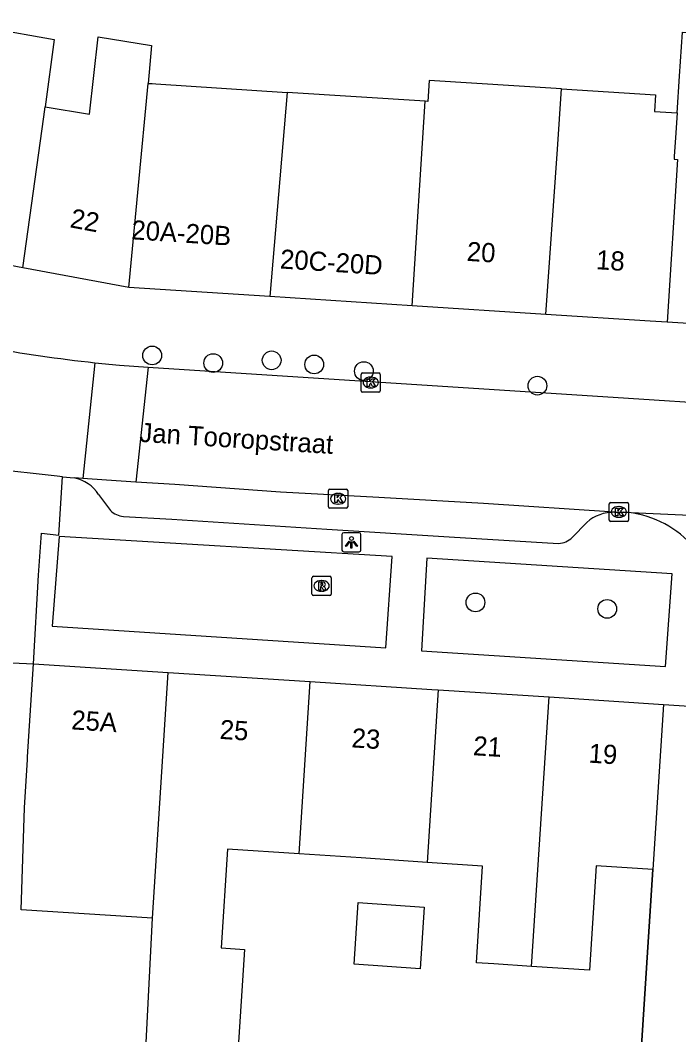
# Model space of a CAD drawing. Extents: x 163010 to 163853, y 382793 to 383982.
# Drawn here: x 163273.4 to 163307.7, y 383427.7 to 383480.6 of the extents above; entities that cross this region are included whole.
import ezdxf

# ---------------------------------------------------------------- set-up
doc = ezdxf.new("R2010")
doc.units = 0
for name, color, linetype in [('IMGEO_Boom', 7, 'Continuous'), ('IMGEO_Kolk', 7, 'Continuous'), ('IMGEO_Lichtpunt', 7, 'Continuous'), ('IMGEO_Muur', 7, 'Continuous'), ('IMGEO_Openbare_ruimte_label', 7, 'Continuous'), ('IMGEO_Pand', 7, 'Continuous'), ('IMGEO_Pand_nummerreeks', 7, 'Continuous'), ('IMGEO_Rijbaan_lokaal_open', 7, 'Continuous'), ('IMGEO_Rioolput', 7, 'Continuous'), ('IMGEO_Voetpad_open', 7, 'Continuous')]:
    doc.layers.add(name, color=color, linetype=linetype)

msp = doc.modelspace()

# ---------------------------------------------------------------- linework, layer by layer
at = {"layer": 'IMGEO_Boom'}
for centre in [(163280.281, 383463.141), (163283.462, 383462.743), (163286.509, 383462.887), (163288.727, 383462.671), (163291.316, 383462.325), (163300.361, 383461.565), (163297.132, 383450.267), (163303.999, 383449.932)]:
    msp.add_circle(centre, 0.489, dxfattribs=at)
at = {"layer": 'IMGEO_Kolk'}
for p, q in [((163291.172, 383461.304), (163291.172, 383462.156)), ((163291.247, 383462.23), (163292.099, 383462.23)), ((163291.66, 383462.01), (163291.685, 383462.01)), ((163292.173, 383462.156), (163292.173, 383461.304)), ((163291.683, 383461.45), (163291.658, 383461.45)), ((163292.099, 383461.23), (163291.247, 383461.23)), ((163289.474, 383455.247), (163289.474, 383456.099)), ((163289.549, 383456.173), (163290.401, 383456.173)), ((163290.475, 383456.099), (163290.475, 383455.247)), ((163289.962, 383455.953), (163289.987, 383455.953)), ((163290.401, 383455.173), (163289.549, 383455.173)), ((163289.985, 383455.393), (163289.96, 383455.393)), ((163304.107, 383454.557), (163304.107, 383455.409)), ((163304.182, 383455.483), (163305.034, 383455.483)), ((163304.595, 383455.263), (163304.62, 383455.263)), ((163305.108, 383455.409), (163305.108, 383454.557)), ((163305.034, 383454.483), (163304.182, 383454.483)), ((163304.618, 383454.703), (163304.593, 383454.703))]:
    msp.add_line(p, q, dxfattribs=at)
for points in [[(163291.172, 383461.304), (163291.172, 383462.156)], [(163291.247, 383462.23), (163292.099, 383462.23)], [(163291.493, 383461.93), (163291.616, 383461.93), (163291.616, 383461.779), (163291.746, 383461.93), (163291.91, 383461.93), (163291.764, 383461.779), (163291.917, 383461.53), (163291.765, 383461.53), (163291.68, 383461.694), (163291.616, 383461.627), (163291.616, 383461.53), (163291.493, 383461.53), (163291.493, 383461.93)], [(163292.173, 383462.156), (163292.173, 383461.304)], [(163292.099, 383461.23), (163291.247, 383461.23)], [(163289.474, 383455.247), (163289.474, 383456.099)], [(163289.549, 383456.173), (163290.401, 383456.173)], [(163290.475, 383456.099), (163290.475, 383455.247)], [(163289.795, 383455.873), (163289.918, 383455.873), (163289.918, 383455.722), (163290.048, 383455.873), (163290.212, 383455.873), (163290.066, 383455.722), (163290.219, 383455.473), (163290.067, 383455.473), (163289.982, 383455.637), (163289.918, 383455.57), (163289.918, 383455.473), (163289.795, 383455.473), (163289.795, 383455.873)], [(163290.401, 383455.173), (163289.549, 383455.173)], [(163304.107, 383454.557), (163304.107, 383455.409)], [(163304.182, 383455.483), (163305.034, 383455.483)], [(163304.428, 383455.183), (163304.551, 383455.183), (163304.551, 383455.032), (163304.681, 383455.183), (163304.845, 383455.183), (163304.699, 383455.032), (163304.852, 383454.783), (163304.7, 383454.783), (163304.615, 383454.947), (163304.551, 383454.88), (163304.551, 383454.783), (163304.428, 383454.783), (163304.428, 383455.183)], [(163305.108, 383455.409), (163305.108, 383454.557)], [(163305.034, 383454.483), (163304.182, 383454.483)]]:
    msp.add_lwpolyline(points, dxfattribs=at)
for centre, start, end in [((163291.249, 383462.154), 91.552, 178.448), ((163291.249, 383462.154), 91.552, 178.448), ((163292.097, 383462.154), 1.552, 88.448), ((163292.097, 383462.154), 1.552, 88.448), ((163291.249, 383461.306), 181.552, 268.448), ((163291.249, 383461.306), 181.552, 268.448), ((163292.097, 383461.306), 271.552, 358.448), ((163292.097, 383461.306), 271.552, 358.448), ((163289.551, 383456.097), 91.552, 178.448), ((163289.551, 383456.097), 91.552, 178.448), ((163290.399, 383456.097), 1.552, 88.448), ((163290.399, 383456.097), 1.552, 88.448), ((163289.551, 383455.249), 181.552, 268.448), ((163289.551, 383455.249), 181.552, 268.448), ((163290.399, 383455.249), 271.552, 358.448), ((163290.399, 383455.249), 271.552, 358.448), ((163304.184, 383455.407), 91.552, 178.448), ((163304.184, 383455.407), 91.552, 178.448), ((163305.032, 383455.407), 1.552, 88.448), ((163305.032, 383455.407), 1.552, 88.448), ((163304.184, 383454.559), 181.552, 268.448), ((163304.184, 383454.559), 181.552, 268.448), ((163305.032, 383454.559), 271.552, 358.448), ((163305.032, 383454.559), 271.552, 358.448)]:
    msp.add_arc(centre, 0.0765, start, end, dxfattribs=at)
for centre, major_axis, ratio, start_param, end_param in [((163291.659, 383461.73), (-0.387, 0.002), 0.722429, 4.712389, 7.853982), ((163291.684, 383461.73), (-0.39, 0.002), 0.717154, 1.570796, 4.712389), ((163289.961, 383455.673), (-0.387, 0.002), 0.722429, 4.712389, 7.853982), ((163289.986, 383455.673), (-0.39, 0.002), 0.717154, 1.570796, 4.712389), ((163304.594, 383454.983), (-0.387, 0.002), 0.722429, 4.712389, 7.853982), ((163304.619, 383454.983), (-0.39, 0.002), 0.717154, 1.570796, 4.712389)]:
    msp.add_ellipse(centre, major_axis=major_axis, ratio=ratio, start_param=start_param, end_param=end_param, dxfattribs=at)
at = {"layer": 'IMGEO_Lichtpunt'}
for p, q in [((163290.169, 383453.805), (163290.169, 383452.998)), ((163290.169, 383453.805), (163290.169, 383452.998)), ((163291.071, 383453.9), (163290.263, 383453.9)), ((163291.071, 383453.9), (163290.263, 383453.9)), ((163291.165, 383452.998), (163291.165, 383453.805)), ((163291.165, 383452.998), (163291.165, 383453.805)), ((163290.263, 383452.904), (163291.071, 383452.904)), ((163290.263, 383452.904), (163291.071, 383452.904))]:
    msp.add_line(p, q, dxfattribs=at)
for points in [[(163290.543, 383453.469), (163290.582, 383453.441), (163290.394, 383453.179), (163290.356, 383453.206), (163290.543, 383453.469)], [(163290.645, 383453.421), (163290.692, 383453.421), (163290.692, 383453.099), (163290.645, 383453.099), (163290.645, 383453.421)], [(163290.755, 383453.441), (163290.793, 383453.468), (163290.98, 383453.206), (163290.941, 383453.178), (163290.755, 383453.441)]]:
    msp.add_lwpolyline(points, dxfattribs=at)
msp.add_circle((163290.668, 383453.603), 0.0994, dxfattribs=at)
for centre, start, end in [((163290.263, 383453.805), 90, 180), ((163290.263, 383453.805), 90, 180), ((163291.071, 383453.805), 0, 90), ((163291.071, 383453.805), 0, 90), ((163290.263, 383452.998), 180, 270), ((163290.263, 383452.998), 180, 270), ((163291.071, 383452.998), 270, 0), ((163291.071, 383452.998), 270, 360)]:
    msp.add_arc(centre, 0.0946, start, end, dxfattribs=at)
at = {"layer": 'IMGEO_Muur'}
msp.add_lwpolyline([(163306.383, 383436.342), (163305.357, 383420.406)], dxfattribs=at)
at = {"layer": 'IMGEO_Pand'}
for points in [[(163269.469, 383480.611), (163271.606, 383480.233), (163271.83, 383480.193), (163275.172, 383479.601), (163274.699, 383476.098)], [(163307.642, 383475.786), (163307.765, 383477.698), (163307.928, 383479.996), (163309.627, 383479.887), (163309.529, 383478.361), (163319.691, 383477.707), (163319.479, 383474.405)], [(163274.699, 383476.098), (163277.008, 383475.723), (163277.473, 383479.751), (163280.25, 383479.3), (163280.064, 383477.321)], [(163279.066, 383466.68), (163280.064, 383477.321)], [(163280.064, 383477.321), (163280.28, 383477.308), (163280.471, 383477.295), (163287.31, 383476.855)], [(163301.618, 383477.038), (163294.725, 383477.481), (163294.654, 383476.383), (163294.517, 383476.392)], [(163287.31, 383476.855), (163286.418, 383466.207)], [(163294.517, 383476.392), (163287.31, 383476.855)], [(163300.805, 383465.282), (163301.416, 383473.897), (163301.618, 383477.038)], [(163301.618, 383477.038), (163306.525, 383476.723), (163306.47, 383475.862), (163307.642, 383475.786)], [(163293.832, 383465.73), (163294.517, 383476.392)], [(163273.545, 383467.715), (163274.629, 383475.579), (163274.699, 383476.098)], [(163307.642, 383475.786), (163307.576, 383474.753), (163307.495, 383473.506), (163307.487, 383473.376), (163307.671, 383473.358), (163307.126, 383464.876)], [(163273.545, 383467.715), (163268.196, 383468.718)], [(163279.066, 383466.68), (163273.545, 383467.715)], [(163286.418, 383466.207), (163279.066, 383466.68)], [(163293.832, 383465.73), (163286.418, 383466.207)], [(163300.805, 383465.282), (163293.832, 383465.73)], [(163307.126, 383464.876), (163306.231, 383464.933), (163300.805, 383465.282)], [(163318.82, 383464.124), (163310.182, 383464.679), (163307.126, 383464.876)], [(163280.296, 383433.809), (163273.459, 383434.249), (163273.619, 383439.566), (163273.78, 383442.078), (163273.789, 383442.212), (163274.101, 383447.067)], [(163274.101, 383447.067), (163281.118, 383446.616)], [(163280.296, 383433.809), (163281.118, 383446.616)], [(163281.118, 383446.616), (163288.516, 383446.14)], [(163287.939, 383437.167), (163288.516, 383446.14)], [(163288.516, 383446.14), (163294.861, 383445.732), (163295.192, 383445.711)], [(163295.192, 383445.711), (163294.613, 383436.705)], [(163295.192, 383445.711), (163300.966, 383445.339)], [(163300.053, 383431.298), (163300.966, 383445.339)], [(163300.966, 383445.339), (163306.938, 383444.955)], [(163306.938, 383444.955), (163306.383, 383436.342)], [(163287.939, 383437.167), (163284.21, 383437.407), (163283.879, 383432.259), (163285.091, 383432.181), (163284.33, 383420.342), (163279.637, 383420.644), (163279.954, 383426.982), (163280.296, 383433.809)], [(163294.613, 383436.705), (163291.17, 383436.959), (163287.939, 383437.167)], [(163300.053, 383431.298), (163298.082, 383431.425), (163297.191, 383431.486), (163297.507, 383436.519), (163294.613, 383436.705)], [(163306.383, 383436.342), (163303.42, 383436.532), (163303.071, 383431.104), (163300.053, 383431.298)], [(163291.02, 383434.625), (163294.464, 383434.391), (163294.257, 383431.172), (163290.813, 383431.409), (163291.02, 383434.625)]]:
    msp.add_lwpolyline(points, dxfattribs=at)
at = {"layer": 'IMGEO_Rijbaan_lokaal_open'}
for points in [[(163277.301, 383462.761), (163276.662, 383456.725)], [(163277.301, 383462.761), (163278.585, 383462.628), (163280.074, 383462.531)], [(163280.074, 383462.531), (163279.437, 383456.539)], [(163280.074, 383462.531), (163305.114, 383460.908), (163309.919, 383460.597), (163329.216, 383459.346)], [(163275.604, 383456.817), (163275.321, 383456.845), (163271.847, 383457.228)], [(163275.604, 383456.817), (163276.215, 383456.757)], [(163276.662, 383456.725), (163276.215, 383456.757)], [(163279.437, 383456.539), (163277.904, 383456.638), (163276.662, 383456.725)], [(163304.383, 383454.966), (163297.559, 383455.416), (163292.089, 383455.731), (163286.968, 383456.017), (163281.467, 383456.408), (163279.437, 383456.539)], [(163304.383, 383454.966), (163304.871, 383454.972)], [(163304.871, 383454.972), (163319.773, 383454.293)]]:
    msp.add_lwpolyline(points, dxfattribs=at)
for centre, radius, start, end in [((163287.021, 383550.08), 87.859, 256.1639, 263.64823), ((163304.514, 383449.713), 5.271, 43.0758, 86.1134)]:
    msp.add_arc(centre, radius, start, end, dxfattribs=at)
at = {"layer": 'IMGEO_Rioolput'}
for p, q in [((163288.612, 383450.703), (163288.612, 383451.555)), ((163288.687, 383451.629), (163289.539, 383451.629)), ((163289.1, 383451.409), (163289.125, 383451.409)), ((163289.613, 383451.555), (163289.613, 383450.703)), ((163289.123, 383450.849), (163289.098, 383450.849)), ((163289.539, 383450.629), (163288.687, 383450.629))]:
    msp.add_line(p, q, dxfattribs=at)
for points in [[(163288.612, 383450.703), (163288.612, 383451.555)], [(163288.687, 383451.629), (163289.539, 383451.629)], [(163289.201, 383451.327), (163288.949, 383451.329), (163288.949, 383450.929)], [(163289.613, 383451.555), (163289.613, 383450.703)], [(163288.949, 383450.929), (163289.073, 383450.929), (163289.073, 383451.091), (163289.084, 383451.091)], [(163289.127, 383451.248), (163289.073, 383451.248), (163289.073, 383451.167)], [(163289.073, 383451.167), (163289.125, 383451.167)], [(163289.131, 383451.062), (163289.202, 383450.929), (163289.342, 383450.929), (163289.277, 383451.055)], [(163289.539, 383450.629), (163288.687, 383450.629)]]:
    msp.add_lwpolyline(points, dxfattribs=at)
for centre, radius, start, end in [((163288.689, 383451.553), 0.0765, 91.552, 178.448), ((163288.689, 383451.553), 0.0765, 91.552, 178.448), ((163289.2, 383451.217), 0.109, 350.3612, 89.416), ((163289.537, 383451.553), 0.0765, 1.552, 88.448), ((163289.537, 383451.553), 0.0765, 1.552, 88.448), ((163289.083, 383451.038), 0.0533, 26.0293, 88.6989), ((163289.109, 383451.356), 0.19, 274.7715, 282.9687), ((163289.133, 383451.152), 0.0964, 77.0061, 93.1865), ((163289.147, 383451.209), 0.0378, 276.6634, 79.6772), ((163289.198, 383451.217), 0.112, 277.5842, 350.9817), ((163289.182, 383451.002), 0.108, 29.5134, 73.7905), ((163288.689, 383450.705), 0.0765, 181.552, 268.448), ((163288.689, 383450.705), 0.0765, 181.552, 268.448), ((163289.537, 383450.705), 0.0765, 271.552, 358.448), ((163289.537, 383450.705), 0.0765, 271.552, 358.448)]:
    msp.add_arc(centre, radius, start, end, dxfattribs=at)
for centre, major_axis, ratio, start_param, end_param in [((163289.099, 383451.129), (-0.387, 0.002), 0.722429, 4.712389, 7.853982), ((163289.124, 383451.129), (-0.39, 0.002), 0.717154, 1.570796, 4.712389)]:
    msp.add_ellipse(centre, major_axis=major_axis, ratio=ratio, start_param=start_param, end_param=end_param, dxfattribs=at)
at = {"layer": 'IMGEO_Voetpad_open'}
for points in [[(163274.101, 383447.067), (163274.348, 383451.687), (163274.512, 383453.87), (163275.414, 383453.779), (163275.604, 383456.817)], [(163277.492, 383455.894), (163278.102, 383455.055)], [(163278.781, 383454.75), (163281.3, 383454.612), (163289.379, 383454.08), (163295.754, 383453.694), (163301.469, 383453.342)], [(163302.168, 383453.649), (163302.939, 383454.442)], [(163292.789, 383452.666), (163275.433, 383453.706), (163275.073, 383449.025), (163292.469, 383447.905), (163292.789, 383452.666)], [(163307.379, 383451.765), (163294.591, 383452.575), (163294.316, 383447.745), (163307.041, 383446.928), (163307.379, 383451.765)], [(163271.465, 383447.191), (163274.101, 383447.067)], [(163306.938, 383444.955), (163309.364, 383444.798)], [(163305.357, 383420.406), (163306.383, 383436.342)]]:
    msp.add_lwpolyline(points, dxfattribs=at)
for centre, radius, start, end in [((163275.85, 383454.84), 1.951, 32.6833, 79.2149), ((163278.887, 383455.895), 1.15, 226.9254, 264.6963), ((163304.33, 383452.859), 2.108, 88.5726, 131.3172), ((163301.431, 383454.378), 1.036, 272.0981, 315.324)]:
    msp.add_arc(centre, radius, start, end, dxfattribs=at)

# ---------------------------------------------------------------- texts
at = {"layer": 'IMGEO_Openbare_ruimte_label'}
msp.add_text('Jan Tooropstraat', height=1, rotation=356.3879, dxfattribs=at).set_placement((163279.599, 383458.641))
at = {"layer": 'IMGEO_Pand_nummerreeks'}
for s, rotation, p in [('22', 349.3774, (163275.954, 383469.827)), ('20A-20B', 356.3216, (163279.175, 383469.198)), ('20', 356.3205, (163296.659, 383468.074)), ('20C-20D', 356.3216, (163286.924, 383467.677)), ('18', 356.3216, (163303.396, 383467.641)), ('25A', 356.3199, (163276.045, 383443.654)), ('25', 356.3216, (163283.781, 383443.158)), ('23', 356.3199, (163290.653, 383442.716)), ('21', 356.3199, (163296.991, 383442.307)), ('19', 356.3199, (163303.008, 383441.921))]:
    msp.add_text(s, height=1, rotation=rotation, dxfattribs=at).set_placement(p)

doc.saveas('drawing.dxf')
